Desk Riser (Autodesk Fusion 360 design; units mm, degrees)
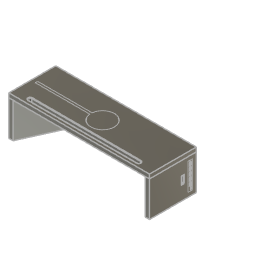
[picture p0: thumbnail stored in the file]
sketch "Top" plane through (0, 0, 0) normal (0, 0, 1) x axis (1, 0, 0)
  line L1 (600, 0) -> (0, 0)
  line L2 (600, 200) -> (600, 0)
  line L3 (0, 200) -> (600, 200)
  line L4 (0, 0) -> (0, 200)
  line L5 (18, 0) -> (18, 200)
  line L6 (0, 100) -> (18, 100)
  line L7 (9, 0) -> (9, 200)
  line L8 (18, 175) -> (9, 175)
  line L9 (0, 175) -> (9, 175)
  line L10 (0, 100) -> (300, 100)
  line L11 (300, 200) -> (300, 100)
  line L12 (300, 0) -> (300, 100)
  line L13 (600, 100) -> (300, 100)
  line L14 (582, 200) -> (582, 0)
  line L15 (250.2506, 105) -> (18, 105)
  line L16 (250.2506, 95) -> (18, 95)
  line L17 (125.1015, 200) -> (125.1015, 105)
  line L18 (125.1015, 0) -> (125.1015, 95)
  line L19 (492.2715, 0) -> (582, 200)
  line L20 (582, 156.0262) -> (512, 0)
  line L21 (582, 178.0131) -> (502.1357, 0)
  line L22 (561.1517, 131.5433) -> (569.3631, 127.8593)
  line L23 (552.9402, 135.2274) -> (561.1517, 131.5433)
  line L24 (18, 156.0262) -> (88, 0)
  line L25 (107.7285, 0) -> (18, 200)
  line L26 (501.2443, 20) -> (98.7557, 20)
  line L27 (89.7828, 40) -> (510.2172, 40)
  line L28 (532, 170) -> (68, 170)
  line L29 (68, 185) -> (532, 185)
  line L30 (532, 177.5) -> (68, 177.5)
  line L31 (18, 95) -> (18, 105)
  line L32 (50, 20) -> (98.7557, 20)
  line L33 (50, 40) -> (50, 20)
  line L34 (89.7828, 40) -> (50, 40)
  line L35 (550, 40) -> (510.2172, 40)
  line L36 (550, 20) -> (550, 40)
  line L37 (550, 20) -> (501.2443, 20)
  circle C1 centre (9, 100) radius 4
  circle C2 centre (9, 25) radius 4
  circle C3 centre (9, 175) radius 4
  circle C4 centre (591, 175) radius 4
  circle C5 centre (591, 100) radius 4
  circle C6 centre (591, 25) radius 4
  arc A1 centre (300, 100) radius 50 clockwise from (250.2506, 105) to (250.2506, 95)
  circle C7 centre (571.7666, 155.2035) radius 4
  circle C8 centre (571.7666, 155.2035) radius 4
  circle C9 centre (506.2291, 9.1238) radius 4
  circle C10 centre (93.7709, 9.1238) radius 4
  circle C11 centre (28.2334, 155.2035) radius 4
  arc A2 centre (532, 177.5) radius 7.5 clockwise from (532, 185) to (532, 170)
  arc A3 centre (68, 177.5) radius 7.5 clockwise from (68, 170) to (68, 185)
  circle C12 centre (536.9292, 77.5527) radius 4
  circle C13 centre (63.0708, 77.5527) radius 4
  point P1 (0, 0)
  point P2 (0, 0)
  point P6 (18, 200)
  point P7 (18, 0)
  point P8 (18, 100)
  point P9 (0, 100)
  point P10 (9, 200)
  point P11 (9, 0)
  point P12 (9, 175)
  point P13 (18, 175)
  point P14 (0, 175)
  point P15 (9, 100)
  point P16 (9, 25)
  point P17 (9, 175)
  point P19 (300, 200)
  point P20 (300, 0)
  point P21 (600, 100)
  point P25 (582, 0)
  point P26 (582, 200)
  point P18 (300, 100)
  point P27 (300, 100)
  point P28 (18, 105)
  point P30 (18, 95)
  point P32 (125.1015, 105)
  point P33 (125.1015, 200)
  point P34 (125.1015, 95)
  point P35 (125.1015, 0)
  point P36 (492.2715, 0)
  point P37 (512, 0)
  point P38 (582, 156.0262)
  point P39 (502.1357, 0)
  point P40 (582, 178.0131)
  point P41 (569.3631, 127.8593)
  point P42 (561.1517, 131.5433)
  point P43 (552.9402, 135.2274)
  point P44 (571.7666, 155.2035)
  point P46 (506.2291, 9.1238)
  point P49 (18, 200)
  point P50 (107.7285, 0)
  point P47 (88, 0)
  point P48 (18, 156.0262)
  point P53 (98.7557, 20)
  point P54 (501.2443, 20)
  point P55 (510.2172, 40)
  point P56 (89.7828, 40)
  point P63 (536.9292, 77.5527)
  point P61 (68, 177.5)
  point P62 (532, 177.5)
  point P66 (50, 40)
  point P67 (550, 40)
  horizontal L1
  vertical L2
  horizontal L3
  vertical L4
  coincident P1 P2
  coincident L3 P6
  coincident L1 P7
  perpendicular L1 L5
  midpoint L5 P8
  midpoint L4 P9
  coincident L3 P10
  coincident L1 P11
  perpendicular L1 L7
  coincident L7 P12
  coincident L5 P13
  perpendicular L5 L8
  coincident L4 P14
  perpendicular L4 L9
  equal L8 L9
  midpoint L7 P15
  coincident L7 P16
  equal C1 C2
  coincident P12 P17
  equal C1 C3
  midpoint L3 P19
  perpendicular L3 L11
  midpoint L1 P20
  equal L11 L12
  midpoint L2 P21
  symmetric C1 L11 C5
  symmetric C2 L11 C6
  symmetric C3 L11 C4
  coincident L1 P25
  coincident L3 P26
  perpendicular L3 L14
  coincident P18 P27
  coincident L5 P28
  perpendicular L5 L15
  coincident L5 P30
  perpendicular L5 L16
  coincident L15 P32
  coincident L3 P33
  perpendicular L3 L17
  coincident L16 P34
  coincident L1 P35
  perpendicular L1 L18
  equal L17 L18
  coincident L1 P36
  coincident L1 P37
  coincident L14 P38
  parallel L19 L20
  coincident L1 P39
  coincident L14 P40
  parallel L20 L21
  coincident L20 P41
  coincident L21 P42
  perpendicular L21 L22
  coincident L19 P43
  perpendicular L19 L23
  equal L22 L23
  coincident L21 P44
  coincident L21 P46
  symmetric L11 P26 P49
  symmetric L11 P36 P50
  symmetric L11 P37 P47
  symmetric L11 P38 P48
  symmetric L11 C8 C11
  symmetric L11 C9 C10
  coincident L25 P53
  coincident L19 P54
  horizontal L26
  coincident L19 P55
  coincident L25 P56
  perpendicular L18 L27
  tangent L28 A2
  tangent A2 L29
  parallel L28 L29
  tangent L29 A3
  tangent L28 A3
  horizontal L30
  coincident L21 P63
  symmetric L11 C12 C13
  parallel L26 L32
  perpendicular L32 L33
  perpendicular L33 L34
  parallel L27 L35
  perpendicular L27 L36
  perpendicular L36 L37
  dimension "riserWidth" distance L2 L4 = 600
  dimension "riserDepth" distance L1 L3 = 200
  dimension "woodThickness" distance L4 L5 = 18
  dimension "connectorDiameter" diameter C1 = 8
  dimension "d12" distance L1 P16 = 25
  dimension "d13" distance L3 P17 = 25
  dimension "chargerDiameter" diameter A1 = 100
  dimension "d15" distance L15 L16 = 10
  dimension "d18" distance P25 P37 = 70
  dimension "d19" distance L19 L20 = 18 (= "woodThickness")
  dimension "d22" diameter C7 = 8 (= "connectorDiameter")
  dimension "d23" distance L2 L14 = 18 (= "woodThickness")
  dimension "d24" distance P40 P44 = 25
  dimension "d27" diameter C9 = 8 (= "connectorDiameter")
  dimension "d28" distance P39 P46 = 10
  dimension "d29" distance L1 L26 = 20
  dimension "d30" distance L26 L27 = 20
  dimension "d31" distance L5 P61 = 50
  dimension "d32" distance L28 L29 = 15
  dimension "d33" distance L3 L29 = 15
  dimension "d34" distance L14 P62 = 50
  dimension "d39" diameter C12 = 8 (= "connectorDiameter")
  dimension "d40" distance P46 P63 = 75
  dimension "d49" distance L5 P66 = 32
  dimension "d50" distance L14 P67 = 32
  dimension "d102" distance P37 P38 = 171.0093
extrude "Extrude3" new body sketch "Top" profile of L1 L2 L3 L4 C1 C2 C3 C4 C5 C6 A1 L15 L16 C7 C8 C9 C10 C11 L26 L27 L28 A2 L29 A3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 along normal blind 18 (= "woodThickness")
extrude "Extrude4" add sketch "Top" profile of A1 L15 L16 L31 along normal blind 2
extrude "Extrude5" add sketch "Top" profile of L26 L27 along normal blind 10
extrude "Extrude6" add sketch "Top" profile of C1 C2 C3 C4 C5 C6 C7 C8 C9 C10 C11 C12 C13 along normal blind 5
fillet "Fillet1" radius 2
sketch "Right" plane through (0, 0, 0) normal (0, 0, 1) x axis (1, 0, 0)
  line L1 (914.5249, 199.599) -> (764.5249, 199.599)
  line L2 (914.5249, -0.401) -> (914.5249, 199.599)
  line L3 (764.5249, -0.401) -> (914.5249, -0.401)
  line L4 (764.5249, 199.599) -> (764.5249, -0.401)
  line L5 (897.0249, 14.599) -> (782.0249, 14.599)
  line L6 (897.0249, 34.599) -> (897.0249, 14.599)
  line L7 (782.0249, 34.599) -> (897.0249, 34.599)
  line L8 (782.0249, 14.599) -> (782.0249, 34.599)
  line L9 (801.0249, 28.349) -> (788.0249, 28.349)
  line L10 (802.0249, 21.849) -> (802.0249, 27.349)
  line L11 (788.0249, 20.849) -> (801.0249, 20.849)
  line L12 (787.0249, 27.349) -> (787.0249, 21.849)
  line L13 (792.3131, 34.599) -> (792.3131, 28.349)
  line L14 (792.3131, 14.599) -> (792.3131, 20.849)
  line L15 (891.0249, 20.849) -> (882.5249, 20.849)
  line L16 (892.0249, 23.349) -> (892.0249, 21.849)
  line L17 (882.5249, 24.349) -> (891.0249, 24.349)
  line L18 (881.5249, 21.849) -> (881.5249, 23.349)
  line L19 (764.5249, 20.849) -> (787.0249, 20.849)
  line L20 (914.5249, 20.849) -> (892.0249, 20.849)
  line L21 (782.0249, 28.349) -> (787.0249, 28.349)
  line L22 (897.0249, 24.349) -> (892.0249, 24.349)
  line L23 (820.0249, 28.349) -> (807.0249, 28.349)
  line L24 (821.0249, 21.849) -> (821.0249, 27.349)
  line L25 (807.0249, 20.849) -> (820.0249, 20.849)
  line L26 (806.0249, 27.349) -> (806.0249, 21.849)
  line L27 (839.0249, 28.349) -> (826.0249, 28.349)
  line L28 (840.0249, 21.849) -> (840.0249, 27.349)
  line L29 (826.0249, 20.849) -> (839.0249, 20.849)
  line L30 (825.0249, 27.349) -> (825.0249, 21.849)
  line L31 (858.0249, 28.349) -> (845.0249, 28.349)
  line L32 (859.0249, 21.849) -> (859.0249, 27.349)
  line L33 (845.0249, 20.849) -> (858.0249, 20.849)
  line L34 (844.0249, 27.349) -> (844.0249, 21.849)
  line L35 (877.0249, 28.349) -> (864.0249, 28.349)
  line L36 (878.0249, 21.849) -> (878.0249, 27.349)
  line L37 (864.0249, 20.849) -> (877.0249, 20.849)
  line L38 (863.0249, 27.349) -> (863.0249, 21.849)
  line L39 (857.5249, 49.599) -> (821.5249, 49.599)
  line L40 (857.5249, 63.599) -> (857.5249, 49.599)
  line L41 (821.5249, 63.599) -> (857.5249, 63.599)
  line L42 (821.5249, 49.599) -> (821.5249, 63.599)
  line L43 (839.5249, 34.599) -> (839.5249, 49.599)
  line L44 (914.5249, 63.599) -> (857.5249, 63.599)
  line L45 (764.5249, 63.599) -> (821.5249, 63.599)
  line L46 (855.5249, 51.599) -> (823.5249, 51.599)
  line L47 (855.5249, 61.599) -> (855.5249, 51.599)
  line L48 (823.5249, 61.599) -> (855.5249, 61.599)
  line L49 (823.5249, 51.599) -> (823.5249, 61.599)
  arc A1 centre (801.0249, 27.349) radius 1 clockwise from (801.0249, 28.349) to (802.0249, 27.349)
  arc A2 centre (788.0249, 27.349) radius 1 clockwise from (787.0249, 27.349) to (788.0249, 28.349)
  arc A3 centre (788.0249, 21.849) radius 1 clockwise from (788.0249, 20.849) to (787.0249, 21.849)
  arc A4 centre (801.0249, 21.849) radius 1 clockwise from (802.0249, 21.849) to (801.0249, 20.849)
  arc A5 centre (820.0249, 21.849) radius 1 clockwise from (821.0249, 21.849) to (820.0249, 20.849)
  arc A6 centre (820.0249, 27.349) radius 1 clockwise from (820.0249, 28.349) to (821.0249, 27.349)
  arc A7 centre (807.0249, 27.349) radius 1 clockwise from (806.0249, 27.349) to (807.0249, 28.349)
  arc A8 centre (807.0249, 21.849) radius 1 clockwise from (807.0249, 20.849) to (806.0249, 21.849)
  arc A9 centre (839.0249, 21.849) radius 1 clockwise from (840.0249, 21.849) to (839.0249, 20.849)
  arc A10 centre (839.0249, 27.349) radius 1 clockwise from (839.0249, 28.349) to (840.0249, 27.349)
  arc A11 centre (826.0249, 27.349) radius 1 clockwise from (825.0249, 27.349) to (826.0249, 28.349)
  arc A12 centre (826.0249, 21.849) radius 1 clockwise from (826.0249, 20.849) to (825.0249, 21.849)
  arc A13 centre (858.0249, 21.849) radius 1 clockwise from (859.0249, 21.849) to (858.0249, 20.849)
  arc A14 centre (858.0249, 27.349) radius 1 clockwise from (858.0249, 28.349) to (859.0249, 27.349)
  arc A15 centre (845.0249, 27.349) radius 1 clockwise from (844.0249, 27.349) to (845.0249, 28.349)
  arc A16 centre (845.0249, 21.849) radius 1 clockwise from (845.0249, 20.849) to (844.0249, 21.849)
  arc A17 centre (877.0249, 21.849) radius 1 clockwise from (878.0249, 21.849) to (877.0249, 20.849)
  arc A18 centre (877.0249, 27.349) radius 1 clockwise from (877.0249, 28.349) to (878.0249, 27.349)
  arc A19 centre (864.0249, 27.349) radius 1 clockwise from (863.0249, 27.349) to (864.0249, 28.349)
  arc A20 centre (864.0249, 21.849) radius 1 clockwise from (864.0249, 20.849) to (863.0249, 21.849)
  arc A21 centre (882.5249, 23.349) radius 1 clockwise from (881.5249, 23.349) to (882.5249, 24.349)
  arc A22 centre (882.5249, 21.849) radius 1 clockwise from (882.5249, 20.849) to (881.5249, 21.849)
  arc A23 centre (891.0249, 21.849) radius 1 clockwise from (892.0249, 21.849) to (891.0249, 20.849)
  arc A24 centre (891.0249, 23.349) radius 1 clockwise from (891.0249, 24.349) to (892.0249, 23.349)
  point P12 (792.3131, 28.349)
  point P13 (792.3131, 34.599)
  point P14 (792.3131, 20.849)
  point P15 (792.3131, 14.599)
  point P18 (764.5249, 20.849)
  point P19 (914.5249, 20.849)
  point P20 (782.0249, 28.349)
  point P21 (897.0249, 24.349)
  point P10 (787.0249, 28.349)
  point P11 (787.0249, 20.849)
  point P16 (892.0249, 20.849)
  point P17 (892.0249, 24.349)
  point P102 (839.5249, 49.599)
  point P103 (839.5249, 34.599)
  point P104 (914.5249, 63.599)
  point P105 (764.5249, 63.599)
  point P98 (821.5249, 49.599)
  point P99 (857.5249, 49.599)
  horizontal L1
  vertical L2
  horizontal L3
  vertical L4
  horizontal L5
  vertical L6
  horizontal L7
  vertical L8
  horizontal L9
  vertical L10
  horizontal L11
  vertical L12
  coincident L9 P12
  coincident L7 P13
  perpendicular L7 L13
  coincident L11 P14
  coincident L5 P15
  perpendicular L5 L14
  equal L13 L14
  horizontal L15
  vertical L16
  horizontal L17
  vertical L18
  coincident L4 P18
  perpendicular L4 L19
  coincident L2 P19
  perpendicular L2 L20
  equal L19 L20
  coincident L8 P20
  perpendicular L8 L21
  coincident L6 P21
  perpendicular L6 L22
  equal L21 L22
  tangent L10 A1
  tangent L9 A1
  coincident P10 L12
  coincident P10 L9
  tangent L12 A2
  tangent L9 A2
  equal A1 A2
  coincident P11 L12
  coincident P11 L11
  tangent L12 A3
  tangent L11 A3
  equal A1 A3
  tangent L11 A4
  tangent L10 A4
  equal A1 A4
  collinear L15 L37
  tangent L17 A21
  tangent L18 A21
  tangent L15 A22
  tangent L18 A22
  equal A21 A22
  coincident P16 L15
  coincident P16 L16
  tangent L15 A23
  tangent L16 A23
  equal A21 A23
  coincident P17 L16
  coincident P17 L17
  tangent L16 A24
  tangent L17 A24
  equal A21 A24
  horizontal L39
  vertical L40
  horizontal L41
  vertical L42
  midpoint L39 P102
  coincident L7 P103
  perpendicular L7 L43
  coincident L2 P104
  perpendicular L2 L44
  coincident L4 P105
  perpendicular L4 L45
  equal L44 L45
  dimension "d53" distance L2 L4 = 150
  dimension "d54" distance L1 L3 = 200 (= "riserDepth")
  dimension "d55" distance L3 L5 = 15
  dimension "d56" distance L5 L7 = 20
  dimension "d57" distance L10 L12 = 15
  dimension "d58" distance L9 L11 = 7.5
  dimension "d66" distance L16 L18 = 10.5
  dimension "d67" distance L15 L17 = 3.5
  dimension "d68" distance P17 P21 = 5
  dimension "d69" radius A1 = 1
  dimension "d74" distance L18 L36 = 3.5
  dimension "d75" radius A21 = 1
  dimension "d76" distance P98 P99 = 36
  dimension "d77" distance L39 L41 = 14
  dimension "d78" distance P102 P103 = 15
  dimension "d79" = -2
  dimension "d72" R-Pattern1-uDistance = 76
  dimension "d73" R-Pattern1-vDistance = 0
extrude "Extrude7" new body sketch "Right" profile of L1 L2 L3 L4 L5 L6 L7 L8 L39 L40 L41 L42 along normal blind 18 (= "woodThickness")
extrude "Extrude8" add sketch "Right" profile of L5 L6 L7 L8 L9 L10 L11 L12 L15 L16 L17 L18 A1 A2 A3 A4 L23 L24 L25 L26 A5 A6 A7 A8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 along normal blind 2
extrude "Extrude9" add sketch "Right" profile of L39 L40 L41 L42 L46 L49 L47 L48 along normal blind 2
component_from_bodies "Body->Comp1"
component_from_bodies "Body->Comp2"
box_primitive "BoxPrimitive1" DistanceX 171 DistanceY 150 DistanceZ 18 (= "woodThickness") OffsetDistanceX 0 OffsetDistanceY 0
draft "Draft1" Angle1 65.8 (= "90 deg - 24.2 deg") Angle2 65.8
draft "Draft2" Angle1 24 (= "114 deg - 90 deg") Angle2 0
component_from_bodies "Body->Comp3"
box_primitive "BoxPrimitive2" DistanceX 200 (= "riserDepth") DistanceY 150 DistanceZ 18 (= "woodThickness") OffsetDistanceX 0 OffsetDistanceY 0
component_from_bodies "Body->Comp4"
sketch "Sketch12" plane through (0, 0, 0) normal (0, 0, -1) x axis (1, 0, 0)
  line L1 (782.0249, -34.599) -> (782.0249, -14.599)
  line L2 (897.0249, -34.599) -> (782.0249, -34.599)
  line L3 (897.0249, -14.599) -> (897.0249, -34.599)
  line L4 (782.0249, -14.599) -> (897.0249, -14.599)
  line L5 (821.5249, -63.599) -> (821.5249, -49.599)
  line L6 (857.5249, -63.599) -> (821.5249, -63.599)
  line L7 (857.5249, -49.599) -> (857.5249, -63.599)
  line L8 (821.5249, -49.599) -> (857.5249, -49.599)
  line L9 (914.5249, 0.401) -> (764.5249, 0.401)
  line L10 (914.5249, -199.599) -> (914.5249, 0.401)
  line L11 (764.5249, -199.599) -> (914.5249, -199.599)
  line L12 (764.5249, 0.401) -> (764.5249, -199.599)
  line L13 (821.5249, -63.599) -> (857.5249, -63.599)
  line L14 (823.5249, -61.599) -> (823.5249, -51.599)
  line L15 (855.5249, -61.599) -> (823.5249, -61.599)
  line L16 (855.5249, -51.599) -> (855.5249, -61.599)
  line L17 (823.5249, -51.599) -> (855.5249, -51.599)
  line L18 (821.5249, -49.599) -> (821.5249, -63.599)
  line L19 (857.5249, -49.599) -> (821.5249, -49.599)
  line L20 (857.5249, -63.599) -> (857.5249, -49.599)
  line L21 (821.5249, -63.599) -> (857.5249, -63.599)
  line L22 (787.0249, -27.349) -> (787.0249, -21.849)
  line L23 (801.0249, -28.349) -> (788.0249, -28.349)
  line L24 (802.0249, -21.849) -> (802.0249, -27.349)
  line L25 (788.0249, -20.849) -> (801.0249, -20.849)
  line L26 (839.0249, -28.349) -> (826.0249, -28.349)
  line L27 (840.0249, -21.849) -> (840.0249, -27.349)
  line L28 (826.0249, -20.849) -> (839.0249, -20.849)
  line L29 (825.0249, -27.349) -> (825.0249, -21.849)
  line L30 (820.0249, -28.349) -> (807.0249, -28.349)
  line L31 (821.0249, -21.849) -> (821.0249, -27.349)
  line L32 (807.0249, -20.849) -> (820.0249, -20.849)
  line L33 (806.0249, -27.349) -> (806.0249, -21.849)
  line L34 (877.0249, -28.349) -> (864.0249, -28.349)
  line L35 (878.0249, -21.849) -> (878.0249, -27.349)
  line L36 (864.0249, -20.849) -> (877.0249, -20.849)
  line L37 (863.0249, -27.349) -> (863.0249, -21.849)
  line L38 (858.0249, -28.349) -> (845.0249, -28.349)
  line L39 (859.0249, -21.849) -> (859.0249, -27.349)
  line L40 (845.0249, -20.849) -> (858.0249, -20.849)
  line L41 (844.0249, -27.349) -> (844.0249, -21.849)
  line L42 (892.0249, -21.849) -> (892.0249, -23.349)
  line L43 (882.5249, -20.849) -> (891.0249, -20.849)
  line L44 (881.5249, -23.349) -> (881.5249, -21.849)
  line L45 (891.0249, -24.349) -> (882.5249, -24.349)
  line L46 (782.0249, -14.599) -> (782.0249, -34.599)
  line L47 (897.0249, -14.599) -> (782.0249, -14.599)
  line L48 (897.0249, -34.599) -> (897.0249, -14.599)
  line L49 (782.0249, -34.599) -> (897.0249, -34.599)
  arc A1 centre (788.0249, -21.849) radius 1 clockwise from (787.0249, -21.849) to (788.0249, -20.849)
  arc A2 centre (788.0249, -27.349) radius 1 clockwise from (788.0249, -28.349) to (787.0249, -27.349)
  arc A3 centre (801.0249, -27.349) radius 1 clockwise from (802.0249, -27.349) to (801.0249, -28.349)
  arc A4 centre (801.0249, -21.849) radius 1 clockwise from (801.0249, -20.849) to (802.0249, -21.849)
  arc A5 centre (826.0249, -27.349) radius 1 clockwise from (826.0249, -28.349) to (825.0249, -27.349)
  arc A6 centre (839.0249, -27.349) radius 1 clockwise from (840.0249, -27.349) to (839.0249, -28.349)
  arc A7 centre (839.0249, -21.849) radius 1 clockwise from (839.0249, -20.849) to (840.0249, -21.849)
  arc A8 centre (826.0249, -21.849) radius 1 clockwise from (825.0249, -21.849) to (826.0249, -20.849)
  arc A9 centre (807.0249, -27.349) radius 1 clockwise from (807.0249, -28.349) to (806.0249, -27.349)
  arc A10 centre (820.0249, -27.349) radius 1 clockwise from (821.0249, -27.349) to (820.0249, -28.349)
  arc A11 centre (820.0249, -21.849) radius 1 clockwise from (820.0249, -20.849) to (821.0249, -21.849)
  arc A12 centre (807.0249, -21.849) radius 1 clockwise from (806.0249, -21.849) to (807.0249, -20.849)
  arc A13 centre (864.0249, -27.349) radius 1 clockwise from (864.0249, -28.349) to (863.0249, -27.349)
  arc A14 centre (877.0249, -27.349) radius 1 clockwise from (878.0249, -27.349) to (877.0249, -28.349)
  arc A15 centre (877.0249, -21.849) radius 1 clockwise from (877.0249, -20.849) to (878.0249, -21.849)
  arc A16 centre (864.0249, -21.849) radius 1 clockwise from (863.0249, -21.849) to (864.0249, -20.849)
  arc A17 centre (845.0249, -27.349) radius 1 clockwise from (845.0249, -28.349) to (844.0249, -27.349)
  arc A18 centre (858.0249, -27.349) radius 1 clockwise from (859.0249, -27.349) to (858.0249, -28.349)
  arc A19 centre (858.0249, -21.849) radius 1 clockwise from (858.0249, -20.849) to (859.0249, -21.849)
  arc A20 centre (845.0249, -21.849) radius 1 clockwise from (844.0249, -21.849) to (845.0249, -20.849)
  arc A21 centre (891.0249, -23.349) radius 1 clockwise from (892.0249, -23.349) to (891.0249, -24.349)
  arc A22 centre (891.0249, -21.849) radius 1 clockwise from (891.0249, -20.849) to (892.0249, -21.849)
  arc A23 centre (882.5249, -21.849) radius 1 clockwise from (881.5249, -21.849) to (882.5249, -20.849)
  arc A24 centre (882.5249, -23.349) radius 1 clockwise from (882.5249, -24.349) to (881.5249, -23.349)
joint "Assemble1" alignAngle -180 alignOffsetX 0 alignOffsetY 0 alignOffsetZ 0
joint "Assemble2" alignAngle 0 alignOffsetX 18 (= "woodThickness") alignOffsetY 0 alignOffsetZ 0
move "Move1"
move "Move2" RotateAngle -90
move "Move3" RotateAngle 24.2
work_plane "WorkPlane1"
mirror_component "MirrorComponent1"
derived_instance "DerivedInstance2"
sketch "Sketch4" plane through (0, 0, 18) normal (0, 0, 1) x axis (-1, 0, 0)
  line L1 (0, 0) -> (0, -200)
  line L2 (-600, 0) -> (0, 0)
  line L3 (-600, -200) -> (-600, 0)
  line L4 (0, -200) -> (-600, -200)
  line L5 (-50, -20) -> (-550, -20)
  line L6 (-50, -40) -> (-50, -20)
  line L7 (-550, -40) -> (-50, -40)
  line L8 (-550, -20) -> (-550, -40)
  line L9 (-18, -105) -> (-18, -95)
  line L10 (-250.2506, -105) -> (-18, -105)
  line L11 (-18, -95) -> (-250.2506, -95)
  line L12 (-532, -187) -> (-68, -187)
  line L13 (-68, -168) -> (-532, -168)
  circle C1 centre (-63.0708, -77.5527) radius 4
  circle C2 centre (-9, -25) radius 4
  arc A1 centre (-300, -100) radius 50 clockwise from (-250.2506, -105) to (-250.2506, -95)
  circle C3 centre (-9, -100) radius 4
  circle C4 centre (-9, -175) radius 4
  circle C5 centre (-536.9292, -77.5527) radius 4
  circle C6 centre (-591, -175) radius 4
  circle C7 centre (-591, -100) radius 4
  circle C8 centre (-93.7709, -9.1238) radius 4
  circle C9 centre (-591, -25) radius 4
  circle C10 centre (-571.7666, -155.2035) radius 4
  circle C11 centre (-28.2334, -155.2035) radius 4
  circle C12 centre (-506.2291, -9.1238) radius 4
  arc A2 centre (-532, -177.5) radius 9.5 clockwise from (-532, -187) to (-532, -168)
  arc A3 centre (-68, -177.5) radius 9.5 clockwise from (-68, -168) to (-68, -187)
move "Move4"
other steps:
derived_base_feature "Derived Base Feature"
move "Move1"
base_feature "Base Feature1"
base_feature "Base Feature1"
base_feature "Base Feature1"
move "Move1"
move "Move1"
base_feature "Base Feature1"
move "Move2"
create_component "CreateComponent1"
remove_body "RemoveBody1"
create_component "CreateComponent2"
remove_body "RemoveBody2"
joint_origin "JointOrigin1"
joint_origin "JointOrigin1"
create_component "CreateComponent3"
remove_body "RemoveBody3"
create_component "CreateComponent4"
create_component "CreateComponent6"
remove_body "RemoveBody4"
joint_origin "JointOrigin1"
joint_origin "JointOrigin2"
